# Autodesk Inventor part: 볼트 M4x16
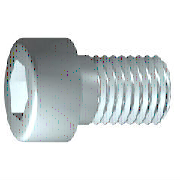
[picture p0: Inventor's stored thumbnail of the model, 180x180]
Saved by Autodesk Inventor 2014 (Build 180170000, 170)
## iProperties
IsCustomPart: 1
Created: 2012-02
Part Number: 볼트 M4x16
Material: 강철, 연강
Description: 6각머리 태핑 나사
Document SubType Name: Modeling
Standard: KS B 1003
Designer: mduedu
Standards Organization: KS
Language: ko-KR
Size Designation: M 4 x 16
Categories: <MemberInstance><Categories><Category DisplayName="조임쇠" InternalName="e4da775c-781d-43d5-af7c-5136215cf5a6" Mnemonic="FSTN"><Category DisplayName="볼트" InternalN
Density: 1 g/cm^3
Appearance: 강철
Author: mduedu
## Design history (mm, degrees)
sketch "스케치1"
  geometry: L1 (-1, 0)-(16, 0); L2 (16, 0)-(16, 2); L3 (16, 2)-(1.75, 2); L4 (1.75, 2)-(1.32, 2); L5 (1.32, 2)-(0, 2); L6 (0, 2)-(0, 3.5); L7 (0, 3.5)-(-4, 3.5); L8 (-4, 3.5)-(-4, 1.732); L9 (-4, 1.732)-(-2, 1.732); L10 (-2, 1.732)-(-1, 0); L11 (-8, 0)-(20, 0) reference; L12 (0, -0.7)-(0, 4.2) reference; L13 (1.75, 2)-(0, 2)
  constraints: 22 end point, 6 parallel, 2 collinear, 2 perpendicular, 1 horizontal, 1 point on line
  dimensions: "d1" = 14.25 distance from line of L3.end L2 (= GEL); "d2" = 0.42952 distance of L4.end L3.end (computed from GAL); "d3" = 4 distance between parallel lines of L8 L6 (= KOH); "d4" = 2 distance of L8.end L9.end (= INTI); "d5" = 60 deg angle of L10 L1; "d6" = 4 diameter of L3 L1 (= GD); "d7" = 4 diameter of L5 L1 (= BDM); "d8" = 3.4641 diameter of L9 L1 (= 1.1547 x SW); "d9" = 7 diameter of L7 L1 (= KOD); "d26" = 16 distance between parallel lines of L12 L2 (= NLG)
revolve "본체" sketch "스케치1" stored, may be unused: angle "d10" = 90 deg
sketch "스케치2"
  geometry: L1 (0, -4.9)-(0, 4.9) reference; L2 (-4.9, 0)-(4.9, 0) reference; L3 (1.732, 0)-(0.866, -1.5); L4 (0.866, -1.5)-(-0.866, -1.5); L5 (-0.866, -1.5)-(-1.732, 0); L6 (-1.732, 0)-(-0.866, 1.5); L7 (-0.866, 1.5)-(0.866, 1.5); L8 (0.866, 1.5)-(1.732, 0); 2 further points
  constraints: 12 end point, 1 coincident, 1 horizontal alignment, 1 point on line, 12 other
extrude "슬롯" join sketch "스케치2" stored distance "d11" = 10; taper "d12" = 0 deg
workplane "Work Plane1"
fillet "Fillet2" dims "d30" = 0.1 (= R)
body "Solid1"
fillet "모깎기1" dims "d17" = 0.4 (= RR)
feature "스레드" dims "d13" = 14.25 (= GEL), "d14" = 0
chamfer "모따기1" distance "d15" = 0.42941 (= -0.5 x SPD + 0.5 x GD); stored, may be unused: second distance "d16" = 0.42941 (= GUL), angle "d27" = 45 deg
other parameters: "GD" = 4 (= NND) [user parameter; used in 2 equation terms], "NLG" = 16 [user parameter; used in 1 equation term], "GEL" = 14.25 [user parameter; used in 2 equation terms], "KOD" = 7 [user parameter; used in 1 equation term], "KOH" = 4 [user parameter; used in 1 equation term], "INTI" = 2 [user parameter; used in 1 equation term], "GAL" = 0.42941 (= 0.61345 x PTC) [user parameter; used in 1 equation term], "GUL" = 0.42941 (= 0.61345 x PTC) [user parameter; used in 1 equation term], "BDM" = 4 (= NND) [user parameter; used in 1 equation term], "SW" = 3 [user parameter; used in 2 equation terms], "RR" = 0.4 [user parameter; used in 1 equation term], "SPD" = 3.14117 (= NND - 1.2269 x PTC) [user parameter; used in 1 equation term], "d19" = 0, "d28" = 0, "d29" = 0, "R" = 0.1 [user parameter; used in 1 equation term], "PHH" = 0.2 [user parameter], "GD1" = 3.14117 (= THREADDIA - 1.2269 x PTC) [user parameter], "THREADDIA" = 4 [user parameter; used in 1 equation term], "FAWI" = 45 deg [user parameter], "TPU" = 14.28571 (computed from PTC) [user parameter], "PTC" = 0.7 [user parameter; used in 5 equation terms], "NND" = 4 [user parameter; used in 3 equation terms], "TOA" = 30 deg [user parameter], "E0" = 3.465 (= 1.155 x SW) [user parameter]
